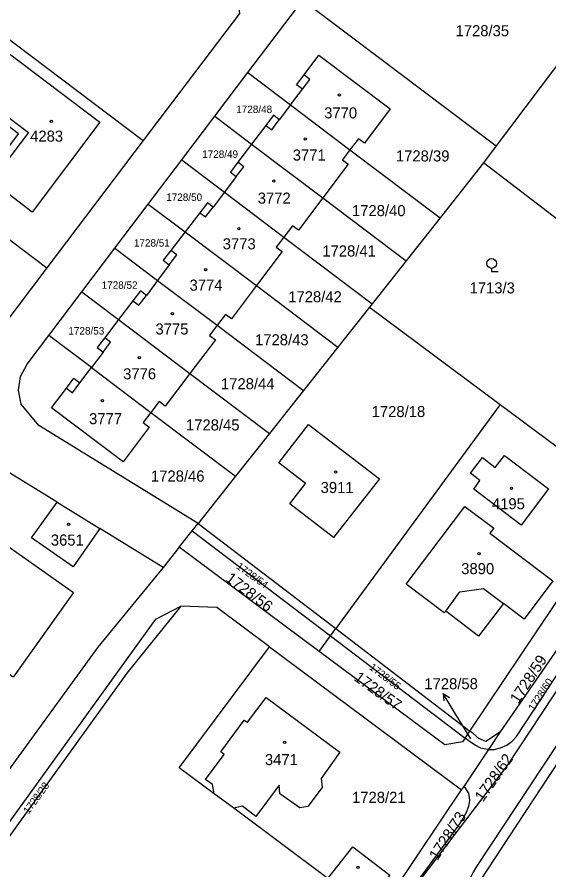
# Model space of a CAD drawing. Extents: x -679220 to -673243, y -1075091 to -1066557.
# Drawn here: x -677095.6 to -677014, y -1072227.6 to -1072096.6 of the extents above; entities that cross this region are included whole.
import ezdxf

# ---------------------------------------------------------------- set-up
doc = ezdxf.new("R2010")
doc.units = 0
for name, color, linetype in [('Hranice parcel', 7, 'Continuous'), ('Parcelní čísla', 7, 'Continuous'), ('Pop  PČ popisy', 7, 'Continuous'), ('Vnitřní kresba', 7, 'Continuous'), ('Značky budov', 7, 'Continuous'), ('Značky kultur', 7, 'Continuous')]:
    doc.layers.add(name, color=color, linetype=linetype)

msp = doc.modelspace()

# ---------------------------------------------------------------- linework, layer by layer
at = {"layer": 'Hranice parcel'}
for p, q in [((-677106.59, -1072092.6), (-677076.2, -1072115.55)), ((-677060.16, -1072105.11), (-677051.71, -1072093.95)), ((-677051.71, -1072093.95), (-677022.03, -1072116.37)), ((-677007.46, -1072096.91), (-677022.03, -1072116.37)), ((-677065.22, -1072111.81), (-677060.16, -1072105.11)), ((-677060.16, -1072105.11), (-677053.59, -1072110.07)), ((-677053.59, -1072110.07), (-677044.48, -1072116.96)), ((-677070.29, -1072118.51), (-677065.22, -1072111.81)), ((-677065.22, -1072111.81), (-677059.57, -1072116.08)), ((-677121.44, -1072112.08), (-677090.98, -1072135.09)), ((-677076.2, -1072115.55), (-677090.98, -1072135.09)), ((-677059.57, -1072116.08), (-677048.65, -1072124.33)), ((-677044.48, -1072116.96), (-677030.64, -1072127.41)), ((-677022.03, -1072116.37), (-677023.98, -1072118.97)), ((-677075.42, -1072125.29), (-677070.29, -1072118.51)), ((-677070.29, -1072118.51), (-677063.73, -1072123.47)), ((-677023.98, -1072118.97), (-677030.64, -1072127.41)), ((-676982.28, -1072150.91), (-677023.98, -1072118.97)), ((-677063.73, -1072123.47), (-677054.62, -1072130.36)), ((-677048.65, -1072124.33), (-677035.85, -1072134)), ((-677080.55, -1072132.07), (-677075.42, -1072125.29)), ((-677075.42, -1072125.29), (-677069.77, -1072129.56)), ((-677030.64, -1072127.41), (-677035.85, -1072134)), ((-677069.77, -1072129.56), (-677058.83, -1072137.82)), ((-677054.62, -1072130.36), (-677041.06, -1072140.6)), ((-677085.62, -1072138.77), (-677080.55, -1072132.07)), ((-677080.55, -1072132.07), (-677073.99, -1072137.02)), ((-677035.85, -1072134), (-677041.06, -1072140.6)), ((-677073.99, -1072137.02), (-677064.87, -1072143.91)), ((-677058.83, -1072137.82), (-677046.33, -1072147.27)), ((-677090.69, -1072145.47), (-677085.62, -1072138.77)), ((-677085.62, -1072138.77), (-677079.97, -1072143.03)), ((-677041.06, -1072140.6), (-677041.46, -1072141.11)), ((-677041.46, -1072141.11), (-677046.33, -1072147.27)), ((-677041.46, -1072141.11), (-677021.42, -1072156.06)), ((-677079.97, -1072143.03), (-677069.03, -1072151.3)), ((-677064.87, -1072143.91), (-677051.61, -1072153.93)), ((-677084.15, -1072150.41), (-677090.69, -1072145.47)), ((-677046.33, -1072147.27), (-677051.61, -1072153.93)), ((-677084.15, -1072150.41), (-677075.01, -1072157.31)), ((-677069.03, -1072151.3), (-677056.82, -1072160.52)), ((-677051.61, -1072153.93), (-677056.82, -1072160.52)), ((-677021.42, -1072156.06), (-677046.63, -1072190.51)), ((-677021.42, -1072156.06), (-676998.86, -1072172.9)), ((-677075.01, -1072157.31), (-677062.04, -1072167.1)), ((-677089.42, -1072171.09), (-677108.59, -1072159.26)), ((-677056.82, -1072160.52), (-677062.04, -1072167.1)), ((-677062.04, -1072167.1), (-677067.77, -1072174.34)), ((-677089.42, -1072171.09), (-677082.85, -1072175.14)), ((-677068.7, -1072175.5), (-677067.77, -1072174.34)), ((-677067.77, -1072174.34), (-677046.63, -1072190.51)), ((-677073.16, -1072181.12), (-677082.85, -1072175.14)), ((-677070.68, -1072177.99), (-677068.7, -1072175.5)), ((-677068.7, -1072175.5), (-677047.45, -1072191.63)), ((-677070.68, -1072177.99), (-677073.16, -1072181.12)), ((-677049.19, -1072194.01), (-677070.68, -1072177.99)), ((-677049.19, -1072194.01), (-677047.45, -1072191.63)), ((-677047.45, -1072191.63), (-677046.63, -1072190.51)), ((-677047.45, -1072191.63), (-677026.81, -1072207.31)), ((-677046.63, -1072190.51), (-677026.1, -1072206.25)), ((-677056.81, -1072193.31), (-677027.35, -1072215.28)), ((-677026.81, -1072207.31), (-677026.1, -1072206.25)), ((-677023.17, -1072209.06), (-677021.37, -1072206.38)), ((-677026.98, -1072214.73), (-677023.17, -1072209.06)), ((-677040.31, -1072234.56), (-677027.35, -1072215.28)), ((-677027.35, -1072215.28), (-677026.98, -1072214.73)), ((-677062.31, -1072218.1), (-677065.31, -1072215.87)), ((-677047.9, -1072228.9), (-677062.31, -1072218.1))]:
    msp.add_line(p, q, dxfattribs=at)
for points in [[(-677091.14, -1072072.31), (-677061.62, -1072094.61), (-677061.42, -1072096.01), (-677076.2, -1072115.55)], [(-677106, -1072106.42), (-677106.51, -1072106.03), (-677101.15, -1072098.9), (-677082.84, -1072112.73), (-677093.22, -1072126.53), (-677100.34, -1072121.12), (-677099.95, -1072120.62), (-677095.34, -1072114.51), (-677106, -1072106.42)], [(-677053.59, -1072110.07), (-677051.77, -1072107.67), (-677052.66, -1072106.97), (-677051.53, -1072105.46), (-677049.26, -1072102.44), (-677038.33, -1072110.66), (-677042.25, -1072115.93), (-677043.19, -1072115.25), (-677044.48, -1072116.96)], [(-677053.59, -1072110.07), (-677055.33, -1072112.36), (-677056.2, -1072111.65), (-677057.41, -1072113.21), (-677059.57, -1072116.08)], [(-677059.57, -1072116.08), (-677061.68, -1072118.87), (-677062.83, -1072120.4), (-677061.92, -1072121.08), (-677063.73, -1072123.47)], [(-677044.48, -1072116.96), (-677045.64, -1072118.5), (-677044.74, -1072119.16), (-677048.65, -1072124.33)], [(-677063.73, -1072123.47), (-677065.47, -1072125.76), (-677066.35, -1072125.09), (-677067.52, -1072126.63), (-677069.77, -1072129.56)], [(-677048.65, -1072124.33), (-677052.4, -1072129.28), (-677053.32, -1072128.66), (-677054.62, -1072130.36)], [(-677069.77, -1072129.56), (-677071.97, -1072132.43), (-677073.12, -1072133.93), (-677072.22, -1072134.63), (-677073.99, -1072137.02)], [(-677090.98, -1072135.09), (-677100.28, -1072147.39), (-677101.76, -1072148.73), (-677103.62, -1072149.47), (-677105.62, -1072149.48), (-677107.58, -1072148.73), (-677119.65, -1072141.33), (-677126.55, -1072136.93), (-677133.31, -1072132.31), (-677135.61, -1072130.68)], [(-677054.62, -1072130.36), (-677055.79, -1072131.89), (-677054.9, -1072132.6), (-677058.83, -1072137.82)], [(-677073.99, -1072137.02), (-677075.72, -1072139.33), (-677076.62, -1072138.63), (-677077.78, -1072140.15), (-677079.97, -1072143.03)], [(-677058.83, -1072137.82), (-677062.68, -1072142.93), (-677063.59, -1072142.24), (-677064.87, -1072143.91)], [(-677079.97, -1072143.03), (-677082.11, -1072145.84), (-677083.26, -1072147.35), (-677082.36, -1072148.06), (-677084.15, -1072150.41)], [(-677064.87, -1072143.91), (-677066.05, -1072145.46), (-677065.13, -1072146.16), (-677069.03, -1072151.3)], [(-677067.77, -1072174.34), (-677092.23, -1072159.33), (-677094.94, -1072156.01), (-677095.33, -1072153.89), (-677095.01, -1072151.77), (-677094.01, -1072149.86), (-677090.69, -1072145.47)], [(-677075.01, -1072157.31), (-677076.2, -1072158.87), (-677075.29, -1072159.56), (-677079.26, -1072164.87), (-677090.26, -1072156.6), (-677087.98, -1072153.57), (-677086.83, -1072152.06), (-677085.91, -1072152.75), (-677084.15, -1072150.41)], [(-677069.03, -1072151.3), (-677072.83, -1072156.32), (-677073.73, -1072155.63), (-677075.01, -1072157.31)], [(-677047.03, -1072176.53), (-677053.73, -1072171.35), (-677051.28, -1072168.19), (-677055.37, -1072165.02), (-677050.84, -1072159.13), (-677039.96, -1072167.5), (-677047.03, -1072176.53)], [(-677014.01, -1072169.02), (-677018.21, -1072174.6), (-677025.47, -1072169.08), (-677024.53, -1072167.77), (-677026.01, -1072166.65), (-677024.16, -1072164.22), (-677022.19, -1072165.76), (-677020.75, -1072163.91), (-677014.01, -1072169.02)], [(-677082.85, -1072175.14), (-677086.97, -1072181.02), (-677093.32, -1072176.54), (-677089.42, -1072171.09)], [(-677022.43, -1072175.06), (-677023.03, -1072175.85), (-677013.34, -1072183.15), (-677017.74, -1072189.03), (-677020.94, -1072186.65), (-677024.75, -1072191.65), (-677029.79, -1072187.85), (-677030, -1072188.09), (-677035.87, -1072183.69), (-677026.86, -1072171.73), (-677022.43, -1072175.06)], [(-677086.89, -1072184.95), (-677096.16, -1072197.96), (-677108.34, -1072189.32), (-677099.14, -1072176.35), (-677086.89, -1072184.95)], [(-677026.1, -1072206.25), (-677010.31, -1072182.77), (-677002.77, -1072178.71)], [(-677073.16, -1072181.12), (-677083.15, -1072193.33), (-677097.67, -1072213.39)], [(-677021.37, -1072206.38), (-677008.05, -1072187.02), (-677006.93, -1072185.42)], [(-677137.29, -1072278.46), (-677138.25, -1072277.77), (-677074.28, -1072189.03), (-677070.45, -1072187.06)], [(-677070.45, -1072187.06), (-677078.7, -1072197.36), (-677100.67, -1072227.78)], [(-677056.81, -1072193.31), (-677064.93, -1072187.26), (-677070.45, -1072187.06)], [(-677041.29, -1072239.09), (-677020.3, -1072211.54), (-677004.4, -1072187.4)], [(-677023.17, -1072209.06), (-677022.36, -1072209.08), (-677021.37, -1072208.84), (-677020.43, -1072208.43), (-677019.61, -1072207.8), (-677018.91, -1072207.08), (-677005.45, -1072186.58)], [(-677000.68, -1072190.31), (-677010.81, -1072205.46), (-677025.05, -1072227.04), (-677025.58, -1072227.92), (-677026.06, -1072228.81), (-677026.31, -1072229.79), (-677026.34, -1072230.8), (-677026.21, -1072231.82), (-677025.88, -1072232.78), (-677025.36, -1072233.67), (-677024.7, -1072234.47), (-677011.5, -1072244.49)], [(-677065.31, -1072215.87), (-677070.68, -1072211.91), (-677056.81, -1072193.31)], [(-677026.81, -1072207.31), (-677027.21, -1072207.9), (-677029.93, -1072208.37), (-677049.19, -1072194.01)], [(-677000.98, -1072193.99), (-677009.55, -1072206.46), (-677019.04, -1072220.85), (-677024.42, -1072229.04), (-677024.78, -1072230), (-677024.76, -1072230.97), (-677024.5, -1072231.92), (-677024.01, -1072232.8), (-677023.32, -1072233.51), (-677014.49, -1072240.22)], [(-677065.31, -1072215.87), (-677065.55, -1072214.46), (-677066.63, -1072213.67), (-677063.79, -1072209.83), (-677064.31, -1072209.44), (-677060.7, -1072204.55), (-677060.19, -1072204.89), (-677057.34, -1072201.07), (-677046.04, -1072209.49), (-677048.9, -1072213.51), (-677048.73, -1072214.89), (-677050.93, -1072217.85), (-677052.19, -1072218.04), (-677055.23, -1072215.86), (-677055.36, -1072214.56), (-677058.94, -1072219.38), (-677060.97, -1072217.79), (-677062.31, -1072218.1)], [(-677023.17, -1072209.06), (-677023.38, -1072209.05), (-677024.39, -1072208.85), (-677025.29, -1072208.4), (-677026.13, -1072207.83), (-677026.81, -1072207.31)], [(-677021.37, -1072206.38), (-677023.64, -1072207.84), (-677024.69, -1072207.39), (-677025.59, -1072206.64), (-677026.1, -1072206.25)], [(-677026.98, -1072214.73), (-677026.28, -1072215.76), (-677026.13, -1072216.83), (-677026.28, -1072217.83), (-677026.67, -1072218.76), (-677027.15, -1072219.65), (-677027.69, -1072220.49), (-677038.82, -1072235.71)], [(-677047.9, -1072228.9), (-677044.06, -1072224.02), (-677038.38, -1072228.38), (-677042.16, -1072233.17)]]:
    msp.add_lwpolyline(points, dxfattribs=at)
at = {"layer": 'Pop  PČ popisy'}
for p, q in [((-677028.62, -1072203.04), (-677030.17, -1072200.47)), ((-677030.17, -1072200.47), (-677029.22, -1072201.07)), ((-677030.17, -1072200.47), (-677030.08, -1072201.58)), ((-677025.94, -1072207.45), (-677028.62, -1072203.04))]:
    msp.add_line(p, q, dxfattribs=at)
at = {"layer": 'Vnitřní kresba'}
for p, q in [((-677051.77, -1072107.67), (-677050.63, -1072106.16)), ((-677050.63, -1072106.16), (-677051.53, -1072105.46)), ((-677056.47, -1072113.87), (-677055.33, -1072112.36)), ((-677057.41, -1072113.21), (-677056.47, -1072113.87)), ((-677061.92, -1072121.08), (-677060.77, -1072119.57)), ((-677060.77, -1072119.57), (-677061.68, -1072118.87)), ((-677066.62, -1072127.27), (-677065.47, -1072125.76)), ((-677067.52, -1072126.63), (-677066.62, -1072127.27)), ((-677071.06, -1072133.11), (-677071.97, -1072132.43)), ((-677072.22, -1072134.63), (-677071.06, -1072133.11)), ((-677076.86, -1072140.84), (-677075.72, -1072139.33)), ((-677077.78, -1072140.15), (-677076.86, -1072140.84)), ((-677081.23, -1072146.52), (-677082.11, -1072145.84)), ((-677082.36, -1072148.06), (-677081.23, -1072146.52)), ((-677087.98, -1072153.57), (-677087.05, -1072154.27)), ((-677087.05, -1072154.27), (-677085.91, -1072152.75)), ((-677029.79, -1072187.85), (-677027.6, -1072184.87)), ((-677027.6, -1072184.87), (-677024.01, -1072184.36)), ((-677024.01, -1072184.36), (-677020.94, -1072186.65))]:
    msp.add_line(p, q, dxfattribs=at)
msp.add_lwpolyline([(-677106, -1072106.42), (-677105.37, -1072105.59), (-677093.79, -1072114.28), (-677099.11, -1072121.25), (-677099.95, -1072120.62)], dxfattribs=at)
at = {"layer": 'Značky budov'}
for centre in [(-677046.11, -1072108.54), (-677090.32, -1072112.57), (-677051.34, -1072115.29), (-677056.16, -1072121.76), (-677061.53, -1072129.06), (-677066.62, -1072135.39), (-677071.72, -1072142.14), (-677076.81, -1072148.89), (-677082.46, -1072155.5), (-677046.68, -1072166.45), (-677019.69, -1072168.94), (-677087.65, -1072174.49), (-677024.66, -1072178.99), (-677054.48, -1072207.98), (-677043.24, -1072227.19)]:
    msp.add_circle(centre, 0.175, dxfattribs=at)
at = {"layer": 'Značky kultur'}
for p, q in [((-677022.75, -1072135.17), (-677022.75, -1072135.67)), ((-677022.75, -1072135.67), (-677021.75, -1072135.67))]:
    msp.add_line(p, q, dxfattribs=at)
msp.add_circle((-677022.75, -1072134.42), 0.75, dxfattribs=at)

# ---------------------------------------------------------------- texts
at = {"layer": 'Parcelní čísla'}
for s, height, p in [('1728/35', 1.7, (-677028.28, -1072099.52)), ('1728/48', 1.14, (-677061.93, -1072111.31)), ('3770', 1.7, (-677048.44, -1072112.14)), ('4283', 1.7, (-677093.55, -1072115.71)), ('1728/49', 1.14, (-677067.16, -1072118.2)), ('3771', 1.7, (-677053.26, -1072118.61)), ('1728/39', 1.7, (-677037.43, -1072118.75)), ('1728/50', 1.14, (-677072.67, -1072124.81)), ('3772', 1.7, (-677058.63, -1072125.23)), ('1728/40', 1.7, (-677044.17, -1072127.15)), ('1728/51', 1.14, (-677077.63, -1072131.83)), ('3773', 1.7, (-677064, -1072132.25)), ('1728/41', 1.7, (-677048.72, -1072133.35)), ('1728/52', 1.14, (-677082.58, -1072138.31)), ('3774', 1.7, (-677069.09, -1072138.59)), ('1713/3', 1.7, (-677026.13, -1072139.02)), ('1728/42', 1.7, (-677053.95, -1072140.38)), ('1728/53', 1.14, (-677087.68, -1072145.33)), ('3775', 1.7, (-677074.32, -1072145.33)), ('1728/43', 1.7, (-677059.04, -1072146.99)), ('3776', 1.7, (-677079.28, -1072152.22)), ('1728/44', 1.7, (-677064.27, -1072153.74)), ('1728/18', 1.7, (-677041.15, -1072158.01)), ('3777', 1.7, (-677084.51, -1072159.11)), ('1728/45', 1.7, (-677069.64, -1072160.07)), ('1728/46', 1.7, (-677075.01, -1072167.92)), ('3911', 1.7, (-677048.98, -1072169.68)), ('4195', 1.7, (-677022.7, -1072172.17)), ('3651', 1.7, (-677090.38, -1072177.75)), ('3890', 1.7, (-677027.41, -1072182.14)), ('1728/58', 1.7, (-677033.07, -1072199.82)), ('3471', 1.7, (-677057.53, -1072211.47)), ('1728/21', 1.7, (-677044.16, -1072217.27))]:
    msp.add_text(s, height=height, dxfattribs=at).set_placement(p)
for s, height, rotation, p in [('1728/54', 1.14, 324, (-677062.02, -1072181.18)), ('1728/56', 1.7, 323, (-677063.7, -1072183.09)), ('1728/59', 1.7, 57, (-677018.64, -1072202.16)), ('1728/55', 1.14, 323, (-677041.62, -1072196.66)), ('1728/57', 1.7, 324, (-677043.99, -1072198.34)), ('1728/60', 1.14, 57, (-677016.26, -1072203.25)), ('1728/62', 1.7, 55, (-677024.07, -1072217.22)), ('1728/28', 1.14, 54, (-677093.78, -1072219.08)), ('1728/73', 1.7, 57, (-677031.05, -1072226.21))]:
    msp.add_text(s, height=height, rotation=rotation, dxfattribs=at).set_placement(p)

doc.saveas('drawing.dxf')
